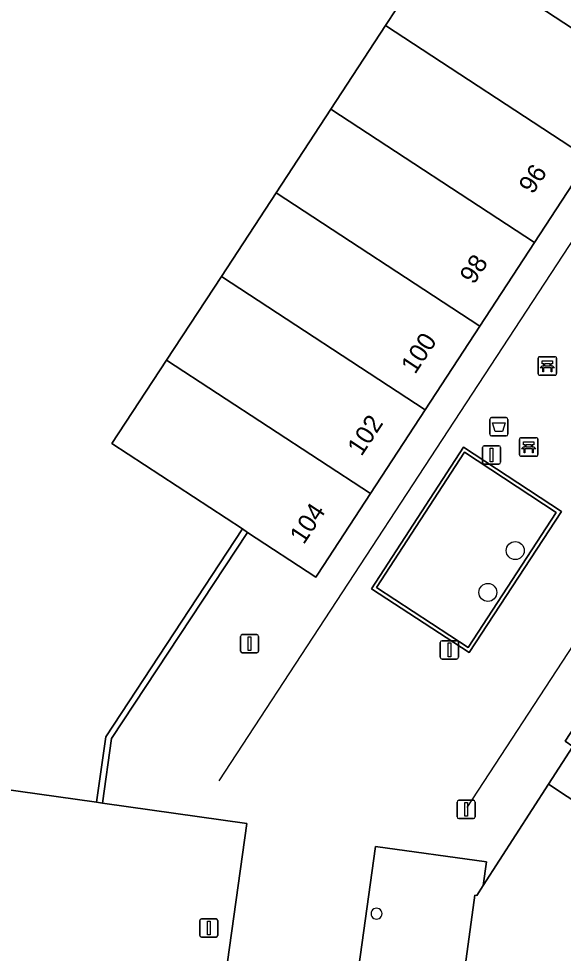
# Model space of a CAD drawing. Extents: x 155640 to 156811, y 382821 to 384049.
# Drawn here: x 156413.1 to 156442.8, y 383696.5 to 383747.5 of the extents above; entities that cross this region are included whole.
import ezdxf

# ---------------------------------------------------------------- set-up
doc = ezdxf.new("R2010")
doc.units = 0
for name, color, linetype in [('IMGEO_Afvalbak', 7, 'Continuous'), ('IMGEO_Bank', 7, 'Continuous'), ('IMGEO_Boom', 7, 'Continuous'), ('IMGEO_Lichtmast', 7, 'Continuous'), ('IMGEO_Lijnafwatering', 7, 'Continuous'), ('IMGEO_Meer_plas_ven_vijver', 7, 'Continuous'), ('IMGEO_Muur', 7, 'Continuous'), ('IMGEO_Pand', 7, 'Continuous'), ('IMGEO_Pand_nummerreeks', 7, 'Continuous'), ('IMGEO_Pand_overbouw', 7, 'Continuous'), ('IMGEO_Rijbaan_lokaal_gesloten', 7, 'Continuous'), ('IMGEO_Voetgangersgebied_open', 7, 'Continuous'), ('IMGEO_Voetpad_open', 7, 'Continuous')]:
    doc.layers.add(name, color=color, linetype=linetype)

msp = doc.modelspace()

# ---------------------------------------------------------------- linework, layer by layer
at = {"layer": 'IMGEO_Afvalbak'}
for p, q in [((156438.818, 383724.836), (156438.818, 383725.636)), ((156438.818, 383725.636), (156438.818, 383724.836)), ((156438.918, 383725.736), (156439.708, 383725.736)), ((156439.708, 383725.736), (156438.918, 383725.736)), ((156439.808, 383725.636), (156439.808, 383724.836)), ((156439.808, 383724.836), (156439.808, 383725.636)), ((156439.708, 383724.736), (156438.918, 383724.736)), ((156438.918, 383724.736), (156439.708, 383724.736))]:
    msp.add_line(p, q, dxfattribs=at)
msp.add_lwpolyline([(156438.961, 383725.45), (156439.665, 383725.45), (156439.516, 383724.98), (156439.11, 383724.98), (156438.961, 383725.45)], dxfattribs=at)
for centre, start, end in [((156438.918, 383725.636), 90, 180), ((156438.918, 383725.636), 90, 180), ((156439.708, 383725.636), 0, 90), ((156439.708, 383725.636), 360, 90), ((156438.918, 383724.836), 180, 270), ((156438.918, 383724.836), 180, 270), ((156439.708, 383724.836), 270, 0), ((156439.708, 383724.836), 270, 0)]:
    msp.add_arc(centre, 0.1, start, end, dxfattribs=at)
at = {"layer": 'IMGEO_Bank'}
for p, q in [((156441.457, 383728.121), (156441.457, 383728.962)), ((156441.457, 383728.962), (156441.457, 383728.121)), ((156441.532, 383729.046), (156442.373, 383729.046)), ((156442.373, 383729.046), (156441.532, 383729.046)), ((156442.457, 383728.971), (156442.457, 383728.13)), ((156442.457, 383728.13), (156442.457, 383728.971)), ((156442.154, 383728.444), (156441.761, 383728.444)), ((156441.766, 383728.552), (156441.766, 383728.658)), ((156441.81, 383728.658), (156441.81, 383728.552)), ((156442.098, 383728.664), (156441.816, 383728.664)), ((156441.816, 383728.546), (156442.098, 383728.546)), ((156442.104, 383728.552), (156442.104, 383728.658)), ((156442.148, 383728.658), (156442.148, 383728.552)), ((156442.382, 383728.046), (156441.541, 383728.046)), ((156441.541, 383728.046), (156442.382, 383728.046)), ((156440.442, 383723.707), (156440.442, 383724.548)), ((156440.442, 383724.548), (156440.442, 383723.707)), ((156440.517, 383724.632), (156441.358, 383724.632)), ((156441.358, 383724.632), (156440.517, 383724.632)), ((156441.442, 383724.557), (156441.442, 383723.716)), ((156441.442, 383723.716), (156441.442, 383724.557)), ((156441.139, 383724.03), (156440.746, 383724.03)), ((156440.751, 383724.138), (156440.751, 383724.244)), ((156440.795, 383724.244), (156440.795, 383724.138)), ((156441.083, 383724.25), (156440.801, 383724.25)), ((156440.801, 383724.132), (156441.083, 383724.132)), ((156441.089, 383724.138), (156441.089, 383724.244)), ((156441.133, 383724.244), (156441.133, 383724.138)), ((156441.367, 383723.632), (156440.526, 383723.632)), ((156440.526, 383723.632), (156441.367, 383723.632))]:
    msp.add_line(p, q, dxfattribs=at)
for points in [[(156441.704, 383728.444), (156441.562, 383728.444), (156441.674, 383728.546), (156441.76, 383728.546)], [(156441.76, 383728.664), (156441.674, 383728.664), (156441.674, 383728.825), (156442.237, 383728.825), (156442.237, 383728.664), (156442.154, 383728.664)], [(156441.754, 383728.437), (156441.754, 383728.23), (156441.711, 383728.23), (156441.711, 383728.437)], [(156442.154, 383728.546), (156442.237, 383728.546), (156442.349, 383728.444), (156442.21, 383728.444)], [(156442.204, 383728.437), (156442.204, 383728.23), (156442.16, 383728.23), (156442.16, 383728.437)], [(156440.745, 383724.25), (156440.659, 383724.25), (156440.659, 383724.411), (156441.222, 383724.411), (156441.222, 383724.25), (156441.139, 383724.25)], [(156440.689, 383724.03), (156440.547, 383724.03), (156440.659, 383724.132), (156440.745, 383724.132)], [(156440.739, 383724.023), (156440.739, 383723.816), (156440.696, 383723.816), (156440.696, 383724.023)], [(156441.139, 383724.132), (156441.222, 383724.132), (156441.334, 383724.03), (156441.195, 383724.03)], [(156441.189, 383724.023), (156441.189, 383723.816), (156441.145, 383723.816), (156441.145, 383724.023)]]:
    msp.add_lwpolyline(points, dxfattribs=at)
for centre, radius, start, end in [((156441.535, 383728.968), 0.0779, 92.4484, 184.2845), ((156441.535, 383728.968), 0.0779, 92.4484, 184.2845), ((156442.379, 383728.968), 0.0779, 2.4484, 94.2845), ((156442.379, 383728.968), 0.0779, 2.4484, 94.2845), ((156441.704, 383728.437), 0.00671, 2.8957, 87.1043), ((156441.761, 383728.437), 0.00671, 92.8957, 177.1043), ((156441.759, 383728.657), 0.00671, 2.8957, 87.1043), ((156441.759, 383728.553), 0.00671, 272.8957, 357.1043), ((156441.816, 383728.657), 0.00671, 92.8957, 177.1043), ((156441.816, 383728.553), 0.00671, 182.8957, 267.1043), ((156442.098, 383728.657), 0.00671, 2.8957, 87.1043), ((156442.098, 383728.553), 0.00671, 272.8957, 357.1043), ((156442.155, 383728.657), 0.00671, 92.8957, 177.1043), ((156442.155, 383728.553), 0.00671, 182.8957, 267.1043), ((156442.153, 383728.437), 0.00671, 2.8957, 87.1043), ((156442.21, 383728.437), 0.00671, 92.8957, 177.1043), ((156441.535, 383728.124), 0.0779, 182.4484, 274.2845), ((156441.535, 383728.124), 0.0779, 182.4484, 274.2845), ((156442.379, 383728.124), 0.0779, 272.4484, 4.2845), ((156442.379, 383728.124), 0.0779, 272.4484, 4.2845), ((156440.52, 383724.554), 0.0779, 92.4484, 184.2845), ((156440.52, 383724.554), 0.0779, 92.4484, 184.2845), ((156441.364, 383724.554), 0.0779, 2.4484, 94.2845), ((156441.364, 383724.554), 0.0779, 2.4484, 94.2845), ((156440.689, 383724.023), 0.00671, 2.8957, 87.1043), ((156440.746, 383724.023), 0.00671, 92.8957, 177.1043), ((156440.744, 383724.243), 0.00671, 2.8957, 87.1043), ((156440.744, 383724.139), 0.00671, 272.8957, 357.1043), ((156440.801, 383724.243), 0.00671, 92.8957, 177.1043), ((156440.801, 383724.139), 0.00671, 182.8957, 267.1043), ((156441.083, 383724.243), 0.00671, 2.8957, 87.1043), ((156441.083, 383724.139), 0.00671, 272.8957, 357.1043), ((156441.14, 383724.243), 0.00671, 92.8957, 177.1043), ((156441.14, 383724.139), 0.00671, 182.8957, 267.1043), ((156441.138, 383724.023), 0.00671, 2.8957, 87.1043), ((156441.195, 383724.023), 0.00671, 92.8957, 177.1043), ((156440.52, 383723.71), 0.0779, 182.4484, 274.2845), ((156440.52, 383723.71), 0.0779, 182.4484, 274.2845), ((156441.364, 383723.71), 0.0779, 272.4484, 4.2845), ((156441.364, 383723.71), 0.0779, 272.4484, 4.2845)]:
    msp.add_arc(centre, radius, start, end, dxfattribs=at)
at = {"layer": 'IMGEO_Boom'}
for centre in [(156440.21, 383718.49), (156438.717, 383716.209)]:
    msp.add_circle(centre, 0.489, dxfattribs=at)
at = {"layer": 'IMGEO_Lichtmast'}
for p, q in [((156438.423, 383723.299), (156438.423, 383724.099)), ((156438.423, 383724.099), (156438.423, 383723.299)), ((156438.523, 383724.199), (156439.313, 383724.199)), ((156439.313, 383724.199), (156438.523, 383724.199)), ((156439.413, 383724.099), (156439.413, 383723.299)), ((156439.413, 383723.299), (156439.413, 383724.099)), ((156439.313, 383723.199), (156438.523, 383723.199)), ((156438.523, 383723.199), (156439.313, 383723.199)), ((156425.233, 383713.017), (156425.233, 383713.817)), ((156425.233, 383713.817), (156425.233, 383713.017)), ((156425.333, 383713.917), (156426.123, 383713.917)), ((156426.123, 383713.917), (156425.333, 383713.917)), ((156426.223, 383713.817), (156426.223, 383713.017)), ((156426.223, 383713.017), (156426.223, 383713.817)), ((156436.124, 383712.681), (156436.124, 383713.481)), ((156436.124, 383713.481), (156436.124, 383712.681)), ((156436.224, 383713.581), (156437.014, 383713.581)), ((156437.014, 383713.581), (156436.224, 383713.581)), ((156437.114, 383713.481), (156437.114, 383712.681)), ((156437.114, 383712.681), (156437.114, 383713.481)), ((156426.123, 383712.917), (156425.333, 383712.917)), ((156425.333, 383712.917), (156426.123, 383712.917)), ((156437.014, 383712.581), (156436.224, 383712.581)), ((156436.224, 383712.581), (156437.014, 383712.581)), ((156437.036, 383703.99), (156437.036, 383704.79)), ((156437.036, 383704.79), (156437.036, 383703.99)), ((156437.136, 383704.89), (156437.926, 383704.89)), ((156437.926, 383704.89), (156437.136, 383704.89)), ((156438.026, 383704.79), (156438.026, 383703.99)), ((156438.026, 383703.99), (156438.026, 383704.79)), ((156437.926, 383703.89), (156437.136, 383703.89)), ((156437.136, 383703.89), (156437.926, 383703.89)), ((156423.01, 383697.528), (156423.01, 383698.328)), ((156423.01, 383698.328), (156423.01, 383697.528)), ((156423.11, 383698.428), (156423.9, 383698.428)), ((156423.9, 383698.428), (156423.11, 383698.428)), ((156424, 383698.328), (156424, 383697.528)), ((156424, 383697.528), (156424, 383698.328)), ((156423.9, 383697.428), (156423.11, 383697.428)), ((156423.11, 383697.428), (156423.9, 383697.428))]:
    msp.add_line(p, q, dxfattribs=at)
for points in [[(156438.843, 383724.074), (156438.993, 383724.074), (156438.993, 383723.324), (156438.843, 383723.324), (156438.843, 383724.074)], [(156425.653, 383713.792), (156425.803, 383713.792), (156425.803, 383713.042), (156425.653, 383713.042), (156425.653, 383713.792)], [(156436.544, 383713.456), (156436.694, 383713.456), (156436.694, 383712.706), (156436.544, 383712.706), (156436.544, 383713.456)], [(156437.456, 383704.765), (156437.606, 383704.765), (156437.606, 383704.015), (156437.456, 383704.015), (156437.456, 383704.765)], [(156423.43, 383698.303), (156423.58, 383698.303), (156423.58, 383697.553), (156423.43, 383697.553), (156423.43, 383698.303)]]:
    msp.add_lwpolyline(points, dxfattribs=at)
for centre, start, end in [((156438.523, 383724.099), 90, 180), ((156438.523, 383724.099), 90, 180), ((156439.313, 383724.099), 0, 90), ((156439.313, 383724.099), 360, 90), ((156438.523, 383723.299), 180, 270), ((156438.523, 383723.299), 180, 270), ((156439.313, 383723.299), 270, 0), ((156439.313, 383723.299), 270, 0), ((156425.333, 383713.817), 90, 180), ((156425.333, 383713.817), 90, 180), ((156426.123, 383713.817), 0, 90), ((156426.123, 383713.817), 360, 90), ((156436.224, 383713.481), 90, 180), ((156436.224, 383713.481), 90, 180), ((156437.014, 383713.481), 0, 90), ((156437.014, 383713.481), 360, 90), ((156425.333, 383713.017), 180, 270), ((156425.333, 383713.017), 180, 270), ((156426.123, 383713.017), 270, 0), ((156426.123, 383713.017), 270, 0), ((156436.224, 383712.681), 180, 270), ((156436.224, 383712.681), 180, 270), ((156437.014, 383712.681), 270, 0), ((156437.014, 383712.681), 270, 0), ((156437.136, 383704.79), 90, 180), ((156437.136, 383704.79), 90, 180), ((156437.926, 383704.79), 0, 90), ((156437.926, 383704.79), 360, 90), ((156437.136, 383703.99), 180, 270), ((156437.136, 383703.99), 180, 270), ((156437.926, 383703.99), 270, 0), ((156437.926, 383703.99), 270, 0), ((156423.11, 383698.328), 90, 180), ((156423.11, 383698.328), 90, 180), ((156423.9, 383698.328), 0, 90), ((156423.9, 383698.328), 360, 90), ((156423.11, 383697.528), 180, 270), ((156423.11, 383697.528), 180, 270), ((156423.9, 383697.528), 270, 0), ((156423.9, 383697.528), 270, 0)]:
    msp.add_arc(centre, 0.1, start, end, dxfattribs=at)
at = {"layer": 'IMGEO_Lijnafwatering'}
for points in [[(156447.726, 383742.098), (156436.226, 383724.532)], [(156436.226, 383724.532), (156424.059, 383705.945)], [(156449.169, 383722.207), (156437.575, 383704.494)]]:
    msp.add_lwpolyline(points, dxfattribs=at)
at = {"layer": 'IMGEO_Meer_plas_ven_vijver'}
msp.add_lwpolyline([(156371.545, 383711.205), (156417.388, 383704.778), (156417.887, 383708.339), (156425.336, 383719.667), (156418.225, 383724.315), (156421.209, 383728.871), (156424.193, 383733.426), (156427.177, 383737.982), (156430.161, 383742.537), (156433.145, 383747.093), (156436.129, 383751.648), (156439.113, 383756.204), (156442.097, 383760.76), (156445.081, 383765.315), (156448.065, 383769.871), (156451.049, 383774.426), (156454.033, 383778.982), (156457.017, 383783.537), (156460.001, 383788.093), (156463.557, 383793.358), (156468.974, 383798.024)], dxfattribs=at)
at = {"layer": 'IMGEO_Muur'}
for points in [[(156437.703, 383712.932), (156442.721, 383720.623), (156437.382, 383724.131), (156432.369, 383716.413)], [(156432.646, 383716.471), (156437.44, 383723.854), (156442.445, 383720.565), (156437.645, 383713.209)], [(156425.619, 383719.482), (156425.336, 383719.667), (156417.887, 383708.339), (156417.388, 383704.778), (156417.705, 383704.734), (156418.203, 383708.256)]]:
    msp.add_lwpolyline(points, close=True, dxfattribs=at)
msp.add_lwpolyline([(156442.019, 383705.761), (156443.341, 383707.811), (156442.937, 383708.11)], dxfattribs=at)
at = {"layer": 'IMGEO_Pand'}
for points in [[(156526.125, 383742.921), (156504.403, 383768.001), (156496.961, 383761.545), (156495.141, 383758.761), (156489.522, 383750.169), (156483.796, 383750.953), (156467.607, 383726.148), (156463.541, 383696.89), (156450.981, 383698.723), (156451.111, 383699.61), (156451.369, 383699.433), (156453.11, 383701.958), (156448.797, 383704.86), (156447.156, 383702.372), (156442.019, 383705.761), (156438.461, 383700.239), (156438.115, 383699.703), (156438.014, 383699.718), (156436.208, 383686.52)], [(156409.602, 383685.242), (156414.878, 383684.502), (156415.328, 383687.843), (156423.21, 383686.732), (156425.581, 383703.63), (156417.705, 383704.734), (156417.388, 383704.778), (156371.545, 383711.205)]]:
    msp.add_lwpolyline(points, dxfattribs=at)
for points in [[(156439.113, 383756.204), (156436.129, 383751.648), (156447.225, 383744.38), (156450.206, 383748.938)], [(156436.129, 383751.648), (156433.145, 383747.093), (156444.244, 383739.822), (156447.225, 383744.38)], [(156433.145, 383747.093), (156430.161, 383742.537), (156441.264, 383735.265), (156444.244, 383739.822)], [(156430.161, 383742.537), (156427.177, 383737.982), (156438.283, 383730.707), (156441.264, 383735.265)], [(156427.177, 383737.982), (156424.193, 383733.426), (156435.302, 383726.149), (156438.283, 383730.707)], [(156424.193, 383733.426), (156421.209, 383728.871), (156432.321, 383721.592), (156435.302, 383726.149)], [(156421.209, 383728.871), (156418.225, 383724.315), (156425.336, 383719.667), (156425.619, 383719.482), (156429.348, 383717.045), (156429.451, 383717.202), (156432.321, 383721.592)]]:
    msp.add_lwpolyline(points, close=True, dxfattribs=at)
for centre, radius, start, end in [((156432.648, 383698.709), 0.3, 120.1773, 239.8227), ((156432.649, 383698.711), 0.298, 359.7726, 120.5732), ((156432.647, 383698.71), 0.3, 240, 0.0367)]:
    msp.add_arc(centre, radius, start, end, dxfattribs=at)
at = {"layer": 'IMGEO_Pand_overbouw'}
msp.add_lwpolyline([(156524.529, 383731.715), (156519.308, 383694.178), (156518.219, 383694.329), (156517.212, 383687.287), (156518.313, 383687.13), (156516.68, 383675.304), (156436.208, 383686.52), (156438.014, 383699.718), (156438.115, 383699.703), (156438.461, 383700.239), (156438.64, 383701.529), (156432.591, 383702.361), (156430.466, 383687.075), (156436.756, 383686.197), (156436.634, 383685.326), (156465.3, 383681.328), (156465.128, 383680.095), (156509.572, 383673.897), (156509.748, 383675.153), (156517.613, 383674.051), (156518.79, 383682.442), (156518.138, 383682.533), (156525.621, 383736.263)], dxfattribs=at)
at = {"layer": 'IMGEO_Rijbaan_lokaal_gesloten'}
msp.add_lwpolyline([(156437.645, 383713.209), (156442.445, 383720.565), (156437.44, 383723.854), (156432.646, 383716.471)], close=True, dxfattribs=at)
at = {"layer": 'IMGEO_Voetgangersgebied_open'}
for points in [[(156430.466, 383687.075), (156432.591, 383702.361), (156438.64, 383701.529), (156438.461, 383700.239), (156442.019, 383705.761), (156443.341, 383707.811), (156442.937, 383708.11), (156445.881, 383712.618), (156445.437, 383712.908), (156448.583, 383717.716), (156451.542, 383722.239), (156454.503, 383726.765), (156457.463, 383731.289), (156460.417, 383735.804), (156463.375, 383740.324), (156466.337, 383744.851), (156469.274, 383749.341)], [(156450.206, 383748.938), (156447.225, 383744.38), (156444.244, 383739.822), (156441.264, 383735.265), (156438.283, 383730.707), (156435.302, 383726.149), (156432.321, 383721.592), (156429.451, 383717.202), (156429.348, 383717.045), (156425.619, 383719.482), (156418.203, 383708.256), (156417.705, 383704.734), (156425.581, 383703.63), (156423.21, 383686.732)]]:
    msp.add_lwpolyline(points, dxfattribs=at)
msp.add_lwpolyline([(156437.703, 383712.932), (156432.369, 383716.413), (156437.382, 383724.131), (156442.721, 383720.623)], close=True, dxfattribs=at)
at = {"layer": 'IMGEO_Voetpad_open'}
msp.add_lwpolyline([(156443.341, 383707.811), (156442.019, 383705.761), (156447.156, 383702.372), (156448.797, 383704.86), (156453.11, 383701.958), (156451.369, 383699.433), (156451.111, 383699.61), (156450.981, 383698.723), (156463.541, 383696.89), (156467.607, 383726.148), (156483.796, 383750.953), (156489.522, 383750.169), (156495.141, 383758.761), (156491.34, 383763.141), (156484.606, 383770.903), (156483.001, 383769.51), (156475.806, 383758.471), (156482.61, 383754.028), (156484.681, 383752.675), (156454.756, 383706.822), (156452.619, 383708.217), (156445.881, 383712.618), (156442.937, 383708.11)], close=True, dxfattribs=at)
msp.add_lwpolyline([(156524.529, 383731.715), (156519.308, 383694.178), (156518.219, 383694.329), (156517.212, 383687.287), (156518.313, 383687.13), (156516.68, 383675.304), (156436.208, 383686.52), (156438.014, 383699.718), (156438.115, 383699.703), (156438.461, 383700.239), (156438.64, 383701.529), (156432.591, 383702.361), (156430.466, 383687.075), (156436.756, 383686.197), (156436.634, 383685.326), (156463.32, 383681.604), (156463.412, 383682.264), (156509.833, 383675.802), (156509.748, 383675.153), (156517.613, 383674.051), (156518.79, 383682.442), (156518.138, 383682.533), (156525.621, 383736.263)], dxfattribs=at)
for centre, radius, start, end in [((156432.648, 383698.709), 0.3, 120.1773, 239.8227), ((156432.649, 383698.711), 0.298, 359.7726, 120.5732), ((156432.647, 383698.71), 0.3, 240, 0.0367)]:
    msp.add_arc(centre, radius, start, end, dxfattribs=at)

# ---------------------------------------------------------------- texts
at = {"layer": 'IMGEO_Pand_nummerreeks'}
for s, p in [('96', (156441.162, 383737.855)), ('98', (156437.947, 383732.939)), ('100', (156434.747, 383728.05)), ('102', (156431.824, 383723.581)), ('104', (156428.681, 383718.775))]:
    msp.add_text(s, height=1, rotation=56.6197, dxfattribs=at).set_placement(p)

doc.saveas('drawing.dxf')
